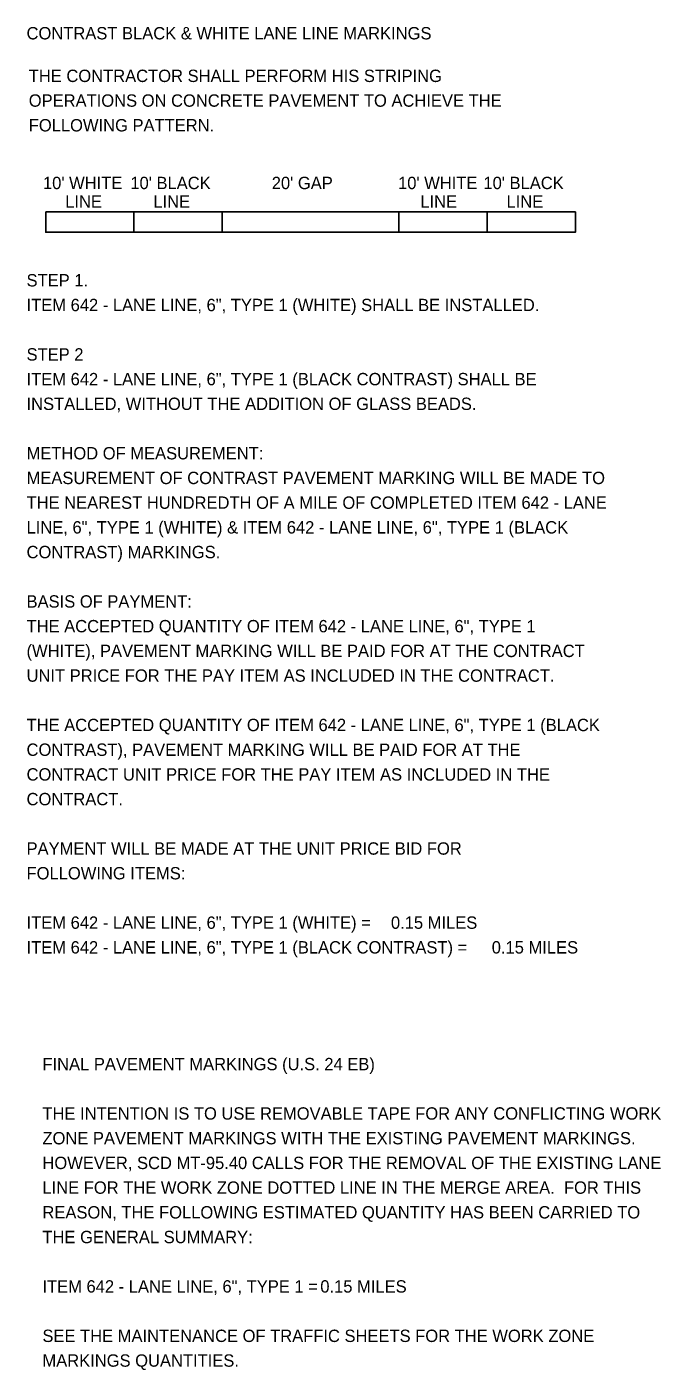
# Model space of a CAD drawing. Extents: x 0 to 42.9, y 0 to 22.
# Drawn here: x 35.67 to 42.85, y 5.92 to 21.14 of the extents above; entities that cross this region are included whole.
import ezdxf

# ---------------------------------------------------------------- set-up
doc = ezdxf.new("R2010")
doc.units = 0
for name, color, linetype in [('PM_P_Lane_Line', 7, 'Continuous'), ('SC_Shading1', 7, 'Continuous'), ('SC_Shading3', 7, 'Continuous'), ('SH_Text', 7, 'Continuous'), ('TX_P_Misc', 7, 'Continuous')]:
    doc.layers.add(name, color=color, linetype=linetype)

msp = doc.modelspace()

# ---------------------------------------------------------------- linework, layer by layer
at = {"layer": 'PM_P_Lane_Line'}
msp.add_lwpolyline([(37.883, 19.044), (39.883, 19.044), (39.883, 18.814), (37.883, 18.814)], close=True, dxfattribs=at)
at = {"layer": 'SC_Shading1'}
for points in [[(36.883, 19.044), (37.883, 19.044), (37.883, 18.814), (36.883, 18.814)], [(40.883, 19.044), (41.883, 19.044), (41.883, 18.814), (40.883, 18.814)]]:
    msp.add_lwpolyline(points, close=True, dxfattribs=at)
at = {"layer": 'SC_Shading3'}
for points in [[(35.883, 19.044), (36.883, 19.044), (36.883, 18.814), (35.883, 18.814)], [(39.883, 19.044), (40.883, 19.044), (40.883, 18.814), (39.883, 18.814)]]:
    msp.add_lwpolyline(points, close=True, dxfattribs=at)

# ---------------------------------------------------------------- texts
at = {"layer": 'SH_Text'}
for s, p in [('THE CONTRACTOR SHALL PERFORM HIS STRIPING ', (35.691, 20.517)), ('OPERATIONS ON CONCRETE PAVEMENT TO ACHIEVE THE ', (35.691, 20.237)), ('FOLLOWING PATTERN.', (35.691, 19.957)), ("10' WHITE", (35.852, 19.303)), ("10' BLACK", (36.842, 19.303)), ("20' GAP", (38.444, 19.303)), ("10' WHITE", (39.875, 19.303)), ("10' BLACK", (40.842, 19.303)), ('LINE', (36.104, 19.093)), ('LINE', (37.103, 19.093)), ('LINE', (40.127, 19.093)), ('LINE', (41.103, 19.093)), ('STEP 1.', (35.666, 18.2)), ('ITEM 642 - LANE LINE, 6", TYPE 1 (WHITE) SHALL BE INSTALLED.', (35.666, 17.92)), ('STEP 2', (35.666, 17.36)), ('ITEM 642 - LANE LINE, 6", TYPE 1 (BLACK CONTRAST) SHALL BE', (35.666, 17.08)), ('INSTALLED, WITHOUT THE ADDITION OF GLASS BEADS.', (35.666, 16.8)), ('METHOD OF MEASUREMENT:', (35.666, 16.24)), ('MEASUREMENT OF CONTRAST PAVEMENT MARKING WILL BE MADE TO ', (35.666, 15.96)), ('THE NEAREST HUNDREDTH OF A MILE OF COMPLETED ITEM 642 - LANE ', (35.666, 15.68)), ('LINE, 6", TYPE 1 (WHITE) & ITEM 642 - LANE LINE, 6", TYPE 1 (BLACK ', (35.666, 15.4)), ('CONTRAST) MARKINGS.', (35.666, 15.12)), ('BASIS OF PAYMENT:', (35.666, 14.56)), ('THE ACCEPTED QUANTITY OF ITEM 642 - LANE LINE, 6", TYPE 1 ', (35.666, 14.28)), ('(WHITE), PAVEMENT MARKING WILL BE PAID FOR AT THE CONTRACT  ', (35.666, 14)), ('UNIT PRICE FOR THE PAY ITEM AS INCLUDED IN THE CONTRACT.', (35.666, 13.72)), ('THE ACCEPTED QUANTITY OF ITEM 642 - LANE LINE, 6", TYPE 1 (BLACK ', (35.666, 13.16)), ('CONTRAST), PAVEMENT MARKING WILL BE PAID FOR AT THE ', (35.666, 12.88)), ('CONTRACT UNIT PRICE FOR THE PAY ITEM AS INCLUDED IN THE ', (35.666, 12.6)), ('CONTRACT.', (35.666, 12.32)), ('PAYMENT WILL BE MADE AT THE UNIT PRICE BID FOR', (35.666, 11.76)), ('FOLLOWING ITEMS:', (35.666, 11.48)), ('ITEM 642 - LANE LINE, 6", TYPE 1 (WHITE) = ', (35.666, 10.92)), ('0.15 MILES', (39.794, 10.92)), ('ITEM 642 - LANE LINE, 6", TYPE 1 (BLACK CONTRAST) = ', (35.666, 10.64)), ('0.15 MILES', (40.936, 10.64)), ('FINAL PAVEMENT MARKINGS (U.S. 24 EB)', (35.846, 9.317)), ('THE INTENTION IS TO USE REMOVABLE TAPE FOR ANY CONFLICTING WORK ', (35.846, 8.757)), ('ZONE PAVEMENT MARKINGS WITH THE EXISTING PAVEMENT MARKINGS.  ', (35.846, 8.477)), ('HOWEVER, SCD MT-95.40 CALLS FOR THE REMOVAL OF THE EXISTING LANE ', (35.846, 8.197)), ('LINE FOR THE WORK ZONE DOTTED LINE IN THE MERGE AREA.  FOR THIS ', (35.846, 7.917)), ('REASON, THE FOLLOWING ESTIMATED QUANTITY HAS BEEN CARRIED TO ', (35.846, 7.637)), ('THE GENERAL SUMMARY:', (35.846, 7.357)), ('ITEM 642 - LANE LINE, 6", TYPE 1 = ', (35.846, 6.797)), ('0.15 MILES', (38.994, 6.797)), ('SEE THE MAINTENANCE OF TRAFFIC SHEETS FOR THE WORK ZONE ', (35.846, 6.237)), ('MARKINGS QUANTITIES.', (35.846, 5.957))]:
    msp.add_text(s, height=0.14, dxfattribs=at).set_placement(p)
at = {"layer": 'TX_P_Misc'}
msp.add_text('CONTRAST BLACK & WHITE LANE LINE MARKINGS', height=0.14, dxfattribs=at).set_placement((35.666, 21))

doc.saveas('drawing.dxf')
